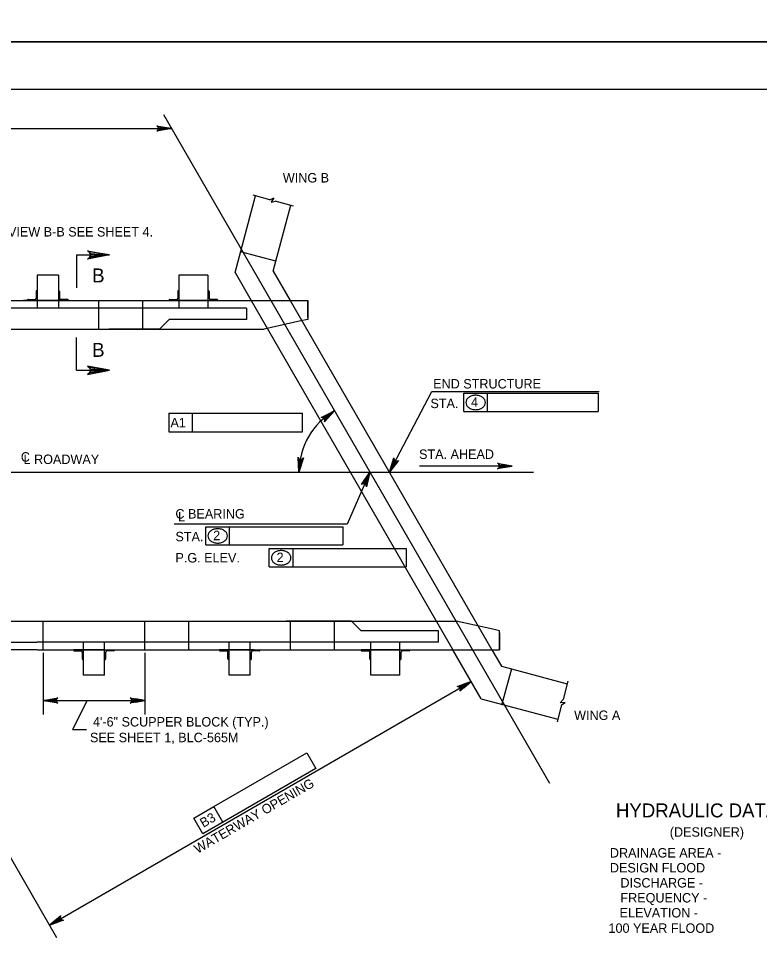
# Model space of a CAD drawing. Extents: x 638175 to 640495, y 294277 to 298435.
# Drawn here: x 638651.1 to 638887, y 296962.4 to 297255 of the extents above; entities that cross this region are included whole.
import ezdxf

# ---------------------------------------------------------------- set-up
doc = ezdxf.new("R2010")
doc.units = 0
for name, color, linetype in [('2', 7, 'Continuous'), ('3', 7, 'Continuous'), ('4', 7, 'Continuous'), ('PLT-BNDY', 7, 'Continuous')]:
    doc.layers.add(name, color=color, linetype=linetype)

msp = doc.modelspace()

# ---------------------------------------------------------------- linework, layer by layer
at = {"layer": '2'}
for p, q in [((638475.46, 297232.46), (639261.46, 297232.46)), ((638720.07, 297174.06), (638726.61, 297198.47)), ((638733.09, 297177.67), (638737.86, 297195.46)), ((638669.66, 297179.67), (638669.66, 297169.18)), ((638669.66, 297179.67), (638680.14, 297179.67)), ((638733.09, 297177.67), (638721.85, 297180.68)), ((638732.25, 297174.51), (638733.09, 297177.67)), ((638720.07, 297174.06), (638725.21, 297165.16)), ((638732.25, 297174.51), (638737.65, 297165.16)), ((638663.83, 297173.26), (638657.11, 297173.26)), ((638663.83, 297173.26), (638657.11, 297173.26)), ((638663.83, 297173.26), (638657.11, 297173.26)), ((638657.11, 297173.26), (638657.11, 297162.77)), ((638663.83, 297173.26), (638663.83, 297162.77)), ((638711.45, 297173.26), (638702.21, 297173.26)), ((638702.21, 297173.26), (638702.21, 297162.77)), ((638711.45, 297173.26), (638711.45, 297162.77)), ((638656.74, 297168.08), (638656.74, 297165.89)), ((638656.92, 297168.26), (638657.11, 297168.26)), ((638657.11, 297168.26), (638657.11, 297165.17)), ((638664.01, 297168.26), (638663.83, 297168.26)), ((638663.83, 297168.26), (638663.83, 297165.17)), ((638664.2, 297168.08), (638664.2, 297165.89)), ((638701.85, 297168.08), (638701.85, 297165.89)), ((638702.03, 297168.26), (638702.21, 297168.26)), ((638702.21, 297168.26), (638702.21, 297165.17)), ((638711.63, 297168.26), (638711.45, 297168.26)), ((638711.45, 297168.26), (638711.45, 297165.17)), ((638711.81, 297168.08), (638711.81, 297165.89)), ((638531.33, 297165.17), (638743.21, 297165.17)), ((638596.1, 297165.17), (638743.2, 297165.17)), ((638655.85, 297165.17), (638652.76, 297165.17)), ((638654.01, 297165.35), (638654.01, 297165.17)), ((638657.11, 297165.17), (638654.01, 297165.17)), ((638654.2, 297165.53), (638656.38, 297165.53)), ((638665.09, 297165.17), (638655.85, 297165.17)), ((638665.09, 297165.17), (638655.85, 297165.17)), ((638663.83, 297165.17), (638657.11, 297165.17)), ((638663.83, 297165.17), (638666.92, 297165.17)), ((638666.74, 297165.53), (638664.56, 297165.53)), ((638665.09, 297165.17), (638668.18, 297165.17)), ((638666.92, 297165.35), (638666.92, 297165.17)), ((638676.64, 297165.17), (638676.64, 297156.04)), ((638690.66, 297165.17), (638690.66, 297156.04)), ((638699.12, 297165.35), (638699.12, 297165.17)), ((638702.21, 297165.17), (638699.12, 297165.17)), ((638699.31, 297165.53), (638701.49, 297165.53)), ((638711.45, 297165.17), (638702.21, 297165.17)), ((638711.45, 297165.17), (638714.54, 297165.17)), ((638714.36, 297165.53), (638712.18, 297165.53)), ((638714.54, 297165.35), (638714.54, 297165.17)), ((638725.21, 297165.16), (638789.4, 297053.99)), ((638737.65, 297165.16), (638801.83, 297053.99)), ((638743.2, 297159.78), (638743.2, 297165.17)), ((638743.2, 297165.17), (638743.2, 297159.14)), ((638743.21, 297159.78), (638743.21, 297165.17)), ((638723.77, 297162.77), (638595.93, 297162.77)), ((638723.77, 297162.77), (638723.77, 297159.14)), ((638696.04, 297156.04), (638699.14, 297159.14)), ((638723.77, 297159.14), (638699.14, 297159.14)), ((638743.2, 297159.14), (638741.02, 297158.65)), ((638578.48, 297156.04), (638729.35, 297156.04)), ((638696.04, 297156.04), (638679.88, 297156.04)), ((638741.02, 297158.65), (638729.35, 297156.04)), ((638669.66, 297142.94), (638669.66, 297153.42)), ((638669.66, 297142.94), (638680.14, 297142.94)), ((638639.57, 297063.11), (638655.73, 297063.11)), ((638639.57, 297063.11), (638790.44, 297063.11)), ((638659.03, 297053.99), (638659.03, 297063.11)), ((638691.36, 297053.99), (638691.37, 297063.11)), ((638705.39, 297053.99), (638705.39, 297063.11)), ((638757.13, 297063.11), (638736.36, 297063.11)), ((638737.73, 297053.99), (638737.73, 297063.11)), ((638751.75, 297053.99), (638751.75, 297063.11)), ((638757.13, 297063.11), (638760.22, 297060.02)), ((638802.11, 297060.51), (638790.44, 297063.11)), ((638784.86, 297060.02), (638760.22, 297060.02)), ((638784.86, 297056.39), (638784.86, 297060.02)), ((638804.29, 297060.02), (638802.11, 297060.51)), ((638804.29, 297053.99), (638804.29, 297060.02)), ((638804.29, 297059.37), (638804.29, 297053.99)), ((638611.85, 297056.39), (638657.02, 297056.39)), ((638784.86, 297056.39), (638657.02, 297056.39)), ((638671.83, 297045.9), (638671.83, 297056.39)), ((638678.56, 297045.9), (638678.56, 297056.39)), ((638718.2, 297045.9), (638718.2, 297056.39)), ((638724.92, 297045.9), (638724.92, 297056.39)), ((638763.3, 297045.9), (638763.3, 297056.39)), ((638772.54, 297045.9), (638772.54, 297056.39)), ((638657.12, 297053.99), (638633.4, 297053.99)), ((638657.19, 297053.99), (638804.29, 297053.99)), ((638668.74, 297053.81), (638668.74, 297053.99)), ((638671.83, 297053.99), (638668.74, 297053.99)), ((638668.92, 297053.63), (638671.1, 297053.63)), ((638678.56, 297053.99), (638671.83, 297053.99)), ((638671.83, 297050.9), (638671.83, 297053.99)), ((638678.56, 297050.9), (638678.56, 297053.99)), ((638678.56, 297053.99), (638681.65, 297053.99)), ((638681.47, 297053.63), (638679.29, 297053.63)), ((638681.65, 297053.81), (638681.65, 297053.99)), ((638715.1, 297053.81), (638715.1, 297053.99)), ((638718.2, 297053.99), (638715.1, 297053.99)), ((638715.29, 297053.63), (638717.47, 297053.63)), ((638726.18, 297053.99), (638716.94, 297053.99)), ((638724.92, 297053.99), (638718.2, 297053.99)), ((638718.2, 297050.9), (638718.2, 297053.99)), ((638724.92, 297050.9), (638724.92, 297053.99)), ((638724.92, 297053.99), (638728.01, 297053.99)), ((638727.83, 297053.63), (638725.65, 297053.63)), ((638728.01, 297053.81), (638728.01, 297053.99)), ((638760.21, 297053.81), (638760.21, 297053.99)), ((638763.3, 297053.99), (638760.21, 297053.99)), ((638760.39, 297053.63), (638762.58, 297053.63)), ((638772.54, 297053.99), (638763.3, 297053.99)), ((638763.3, 297050.9), (638763.3, 297053.99)), ((638772.54, 297050.9), (638772.54, 297053.99)), ((638772.54, 297053.99), (638775.63, 297053.99)), ((638775.45, 297053.63), (638773.27, 297053.63)), ((638775.63, 297053.81), (638775.63, 297053.99)), ((638798.39, 297038.42), (638789.4, 297053.99)), ((638801.83, 297053.99), (638804.86, 297048.74)), ((638671.47, 297051.08), (638671.47, 297053.27)), ((638671.65, 297050.9), (638671.83, 297050.9)), ((638678.74, 297050.9), (638678.56, 297050.9)), ((638678.92, 297051.08), (638678.92, 297053.27)), ((638717.83, 297051.08), (638717.83, 297053.27)), ((638718.01, 297050.9), (638718.2, 297050.9)), ((638725.1, 297050.9), (638724.92, 297050.9)), ((638725.29, 297051.08), (638725.29, 297053.27)), ((638762.94, 297051.08), (638762.94, 297053.27)), ((638763.12, 297050.9), (638763.3, 297050.9)), ((638772.72, 297050.9), (638772.54, 297050.9)), ((638772.9, 297051.08), (638772.9, 297053.27)), ((638804.86, 297048.74), (638808.02, 297047.89)), ((638808.02, 297047.89), (638805, 297036.65)), ((638808.02, 297047.89), (638825.81, 297043.12)), ((638678.56, 297045.9), (638671.83, 297045.9)), ((638724.92, 297045.9), (638718.2, 297045.9)), ((638724.92, 297045.9), (638718.2, 297045.9)), ((638772.54, 297045.9), (638763.3, 297045.9)), ((638798.39, 297038.42), (638822.79, 297031.88))]:
    msp.add_line(p, q, dxfattribs=at)
for points in [[(638680.14, 297179.67), (638673.15, 297178.36), (638673.69, 297178.73), (638673.97, 297179.2), (638674.05, 297179.67), (638673.97, 297180.14), (638673.69, 297180.61), (638673.15, 297180.98), (638680.14, 297179.67), (638673.69, 297180.61), (638673.97, 297180.14), (638680.14, 297179.67), (638674.05, 297179.67), (638673.97, 297179.2), (638680.14, 297179.67), (638673.69, 297178.73)], [(638680.14, 297142.94), (638673.15, 297144.25), (638673.69, 297143.87), (638673.97, 297143.41), (638674.05, 297142.94), (638673.97, 297142.47), (638673.69, 297142), (638673.15, 297141.63), (638680.14, 297142.94), (638673.69, 297142), (638673.97, 297142.47), (638680.14, 297142.94), (638674.05, 297142.94), (638673.97, 297143.41), (638680.14, 297142.94), (638673.69, 297143.87)]]:
    msp.add_lwpolyline(points, dxfattribs=at)
for centre, radius, start, end in [((638656.92, 297168.08), 0.182, 90, 179.9984), ((638664.01, 297168.08), 0.182, 0.0016, 90), ((638702.03, 297168.08), 0.182, 90, 179.9984), ((638711.63, 297168.08), 0.182, 0.0016, 90), ((638654.2, 297165.35), 0.182, 90, 179.9984), ((638656.38, 297165.89), 0.364, 270, 359.9984), ((638664.56, 297165.89), 0.364, 180.0016, 270), ((638666.74, 297165.35), 0.182, 0.0016, 90), ((638699.31, 297165.35), 0.182, 90, 179.9984), ((638701.49, 297165.89), 0.364, 270, 359.9984), ((638712.18, 297165.89), 0.364, 180.0016, 270), ((638714.36, 297165.35), 0.182, 0.0016, 90), ((638668.92, 297053.81), 0.182, 180.0016, 270), ((638671.1, 297053.27), 0.364, 0.0016, 90), ((638679.29, 297053.27), 0.364, 90, 179.9984), ((638681.47, 297053.81), 0.182, 270, 359.9984), ((638715.29, 297053.81), 0.182, 180.0016, 270), ((638717.47, 297053.27), 0.364, 0.0016, 90), ((638725.65, 297053.27), 0.364, 90, 179.9984), ((638727.83, 297053.81), 0.182, 270, 359.9984), ((638760.39, 297053.81), 0.182, 180.0016, 270), ((638762.58, 297053.27), 0.364, 0.0016, 90), ((638773.27, 297053.27), 0.364, 90, 179.9984), ((638775.45, 297053.81), 0.182, 270, 359.9984), ((638671.65, 297051.08), 0.182, 180.0016, 270), ((638678.74, 297051.08), 0.182, 270, 359.9984), ((638718.01, 297051.08), 0.182, 180.0016, 270), ((638725.1, 297051.08), 0.182, 270, 359.9984), ((638763.12, 297051.08), 0.182, 180.0016, 270), ((638772.72, 297051.08), 0.182, 270, 359.9984)]:
    msp.add_arc(centre, radius, start, end, dxfattribs=at)
at = {"layer": '3'}
for p, q in [((638697.27, 297224.34), (638820.13, 297011.53)), ((638731.16, 297197.25), (638725.82, 297198.68)), ((638731.16, 297197.25), (638732.41, 297197.79)), ((638732.41, 297197.79), (638731.55, 297196.49)), ((638731.55, 297196.49), (638732.89, 297196.79)), ((638738.73, 297195.22), (638732.89, 297196.79)), ((638826.04, 297043.99), (638824.48, 297038.16)), ((638824.01, 297036.42), (638822.58, 297031.09)), ((638823.55, 297037.15), (638824.48, 297038.16)), ((638825.11, 297037.24), (638823.55, 297037.15)), ((638824.01, 297036.42), (638825.11, 297037.24))]:
    msp.add_line(p, q, dxfattribs=at)
at = {"layer": '4'}
for p, q in [((638508.41, 297219.92), (638699.81, 297219.92)), ((638769.19, 297110.53), (638782.76, 297136.25)), ((638782.76, 297136.25), (638835.95, 297136.25)), ((638792.86, 297135.63), (638800.44, 297135.63)), ((638792.86, 297129.87), (638792.86, 297135.63)), ((638800.44, 297129.87), (638800.44, 297135.63)), ((638800.44, 297135.63), (638835.62, 297135.63)), ((638835.62, 297135.63), (638835.62, 297129.87)), ((638792.86, 297129.87), (638835.62, 297129.87)), ((638699, 297129.26), (638698.99, 297123.36)), ((638699, 297129.26), (638706.56, 297129.26)), ((638706.56, 297123.36), (638706.56, 297129.26)), ((638706.56, 297129.26), (638741.52, 297129.26)), ((638741.51, 297123.36), (638741.52, 297129.26)), ((638698.99, 297123.36), (638741.51, 297123.36)), ((638805.42, 297112.46), (638778.78, 297112.46)), ((638530.06, 297110.53), (638815.07, 297110.53)), ((638762.97, 297110.53), (638755.79, 297093.93)), ((638755.79, 297093.93), (638700.72, 297093.93)), ((638710.77, 297093.17), (638718.35, 297093.17)), ((638710.77, 297087.4), (638710.77, 297093.17)), ((638718.35, 297087.4), (638718.35, 297093.17)), ((638718.35, 297093.17), (638754.35, 297093.17)), ((638754.35, 297093.17), (638754.35, 297087.4)), ((638710.77, 297087.4), (638754.35, 297087.4)), ((638730.96, 297080.43), (638730.96, 297086.2)), ((638730.96, 297086.2), (638738.54, 297086.2)), ((638738.54, 297080.43), (638738.54, 297086.2)), ((638738.54, 297086.2), (638774.54, 297086.2)), ((638774.54, 297086.2), (638774.54, 297080.43)), ((638730.96, 297080.43), (638774.54, 297080.43)), ((638659.03, 297053.06), (638659.03, 297033.43)), ((638691.36, 297053.06), (638691.36, 297033.43)), ((638616.34, 297043.74), (638663.26, 296962.47)), ((638661.02, 296966.36), (638795.25, 297043.86)), ((638659.03, 297037.86), (638691.36, 297037.86)), ((638672.98, 297037.86), (638668.39, 297028.63)), ((638668.39, 297028.63), (638672.82, 297028.63)), ((638713.34, 297004.12), (638742.92, 297021.16)), ((638742.92, 297021.16), (638745.8, 297016.16)), ((638745.8, 297016.16), (638709.82, 296995.43)), ((638706.94, 297000.43), (638713.34, 297004.12)), ((638716.22, 296999.12), (638713.34, 297004.12)), ((638709.82, 296995.43), (638706.94, 297000.43))]:
    msp.add_line(p, q, dxfattribs=at)
for points in [[(638699.81, 297219.92), (638695.15, 297219.05), (638695.51, 297219.3), (638695.7, 297219.61), (638695.75, 297219.92), (638695.7, 297220.24), (638695.51, 297220.55), (638695.15, 297220.8), (638699.81, 297219.92), (638695.51, 297220.55), (638695.7, 297220.24), (638699.81, 297219.92), (638695.75, 297219.92), (638695.7, 297219.61), (638699.81, 297219.92), (638695.51, 297219.3)], [(638751.7, 297130.05), (638748.53, 297126.53), (638748.66, 297126.94), (638748.62, 297127.3), (638748.47, 297127.58), (638748.24, 297127.8), (638747.91, 297127.93), (638747.47, 297127.91), (638751.7, 297130.05), (638747.91, 297127.93), (638748.24, 297127.8), (638751.7, 297130.05), (638748.47, 297127.58), (638748.62, 297127.3), (638751.7, 297130.05), (638748.66, 297126.94)], [(638740.43, 297110.52), (638740.14, 297115.25), (638740.34, 297114.86), (638740.63, 297114.64), (638740.93, 297114.55), (638741.25, 297114.57), (638741.58, 297114.71), (638741.87, 297115.04), (638740.43, 297110.52), (638741.58, 297114.71), (638741.25, 297114.57), (638740.43, 297110.52), (638740.93, 297114.55), (638740.63, 297114.64), (638740.43, 297110.52), (638740.34, 297114.86)], [(638769.19, 297110.53), (638770.59, 297115.06), (638770.64, 297114.63), (638770.83, 297114.32), (638771.08, 297114.12), (638771.38, 297114.03), (638771.75, 297114.05), (638772.13, 297114.25), (638769.19, 297110.53), (638771.75, 297114.05), (638771.38, 297114.03), (638769.19, 297110.53), (638771.08, 297114.12), (638770.83, 297114.32), (638769.19, 297110.53), (638770.64, 297114.63)], [(638808.31, 297112.46), (638803.65, 297111.59), (638804, 297111.84), (638804.19, 297112.15), (638804.24, 297112.46), (638804.19, 297112.78), (638804, 297113.09), (638803.65, 297113.34), (638808.31, 297112.46), (638804, 297113.09), (638804.19, 297112.78), (638808.31, 297112.46), (638804.24, 297112.46), (638804.19, 297112.15), (638808.31, 297112.46), (638804, 297111.84)], [(638762.97, 297110.53), (638761.92, 297105.91), (638761.84, 297106.34), (638761.62, 297106.63), (638761.36, 297106.8), (638761.05, 297106.88), (638760.69, 297106.83), (638760.32, 297106.6), (638762.97, 297110.53), (638760.69, 297106.83), (638761.05, 297106.88), (638762.97, 297110.53), (638761.36, 297106.8), (638761.62, 297106.63), (638762.97, 297110.53), (638761.84, 297106.34)], [(638795.25, 297043.86), (638791.65, 297040.77), (638791.84, 297041.17), (638791.84, 297041.53), (638791.73, 297041.83), (638791.53, 297042.07), (638791.21, 297042.25), (638790.77, 297042.29), (638795.25, 297043.86), (638791.21, 297042.25), (638791.53, 297042.07), (638795.25, 297043.86), (638791.73, 297041.83), (638791.84, 297041.53), (638795.25, 297043.86), (638791.84, 297041.17)], [(638659.03, 297037.86), (638663.69, 297038.73), (638663.33, 297038.48), (638663.14, 297038.17), (638663.09, 297037.86), (638663.14, 297037.54), (638663.33, 297037.23), (638663.69, 297036.98), (638659.03, 297037.86), (638663.33, 297037.23), (638663.14, 297037.54), (638659.03, 297037.86), (638663.09, 297037.86), (638663.14, 297038.17), (638659.03, 297037.86), (638663.33, 297038.48)], [(638691.36, 297037.86), (638686.7, 297036.98), (638687.06, 297037.23), (638687.25, 297037.54), (638687.3, 297037.86), (638687.25, 297038.17), (638687.06, 297038.48), (638686.7, 297038.73), (638691.36, 297037.86), (638687.06, 297038.48), (638687.25, 297038.17), (638691.36, 297037.86), (638687.3, 297037.86), (638687.25, 297037.54), (638691.36, 297037.86), (638687.06, 297037.23)], [(638661.02, 296966.36), (638664.62, 296969.45), (638664.43, 296969.05), (638664.42, 296968.69), (638664.53, 296968.39), (638664.74, 296968.15), (638665.05, 296967.97), (638665.49, 296967.93), (638661.02, 296966.36), (638665.05, 296967.97), (638664.74, 296968.15), (638661.02, 296966.36), (638664.53, 296968.39), (638664.42, 296968.69), (638661.02, 296966.36), (638664.43, 296969.05)]]:
    msp.add_lwpolyline(points, dxfattribs=at)
for points in [[(638805.42, 297112.95), (638805.42, 297111.98), (638808.31, 297112.46)], [(638762.25, 297107.63), (638761.35, 297108.02), (638762.97, 297110.53)], [(638792.4, 297042.8), (638792.9, 297041.93), (638795.25, 297043.86)], [(638661.98, 297038.35), (638661.98, 297037.36), (638659.03, 297037.86)], [(638688.41, 297038.35), (638688.41, 297037.36), (638691.36, 297037.86)], [(638663.36, 296968.29), (638663.86, 296967.43), (638661.01, 296966.36)], [(638663.86, 296967.43), (638663.36, 296968.29), (638661.02, 296966.36)]]:
    msp.add_lwpolyline(points, close=True, dxfattribs=at)
for centre, radius, start, end in [((638795.24, 297132.7), 1.71, 150.6308, 180), ((638795.24, 297132.7), 1.71, 180, 209.3692), ((638795.92, 297132.32), 2.49, 126.3544, 150.6308), ((638796.36, 297131.72), 3.23, 106.9552, 126.3544), ((638796.65, 297130.78), 4.22, 90, 106.9552), ((638796.65, 297130.78), 4.22, 73.0448, 90), ((638796.94, 297131.72), 3.23, 53.6456, 73.0448), ((638797.38, 297132.32), 2.49, 29.3692, 53.6456), ((638798.05, 297132.7), 1.71, 0, 29.3692), ((638798.05, 297132.7), 1.71, 330.6308, 0), ((638762.97, 297110.53), 22.54, 119.9992, 179.9979), ((638795.92, 297133.08), 2.49, 209.3692, 233.6456), ((638796.36, 297133.68), 3.23, 233.6456, 253.0448), ((638796.65, 297134.63), 4.22, 253.0448, 270), ((638796.65, 297134.63), 4.22, 270, 286.9552), ((638796.94, 297133.68), 3.23, 286.9552, 306.3544), ((638797.38, 297133.08), 2.49, 306.3544, 330.6308), ((638713.82, 297089.85), 2.49, 126.3544, 150.6308), ((638714.27, 297089.25), 3.23, 106.9552, 126.3544), ((638714.55, 297088.31), 4.22, 90, 106.9552), ((638714.55, 297088.31), 4.22, 73.0448, 90), ((638714.84, 297089.25), 3.23, 53.6456, 73.0448), ((638715.28, 297089.85), 2.49, 29.3692, 53.6456), ((638713.15, 297090.24), 1.71, 150.6308, 180), ((638713.15, 297090.24), 1.71, 180, 209.3692), ((638713.82, 297090.62), 2.49, 209.3692, 233.6456), ((638714.27, 297091.22), 3.23, 233.6456, 253.0448), ((638714.84, 297091.22), 3.23, 286.9552, 306.3544), ((638715.28, 297090.62), 2.49, 306.3544, 330.6308), ((638715.96, 297090.24), 1.71, 0, 29.3692), ((638715.96, 297090.24), 1.71, 330.6308, 0), ((638714.55, 297092.16), 4.22, 253.0448, 270), ((638714.55, 297092.16), 4.22, 270, 286.9552), ((638733.34, 297083.27), 1.71, 150.6308, 180), ((638733.34, 297083.27), 1.71, 180, 209.3692), ((638734.01, 297082.89), 2.49, 126.3544, 150.6308), ((638734.45, 297082.29), 3.23, 106.9552, 126.3544), ((638734.74, 297081.34), 4.22, 90, 106.9552), ((638734.74, 297081.34), 4.22, 73.0448, 90), ((638735.03, 297082.29), 3.23, 53.6456, 73.0448), ((638735.47, 297082.89), 2.49, 29.3692, 53.6456), ((638736.15, 297083.27), 1.71, 0, 29.3692), ((638736.15, 297083.27), 1.71, 330.6308, 0), ((638734.01, 297083.65), 2.49, 209.3692, 233.6456), ((638734.45, 297084.25), 3.23, 233.6456, 253.0448), ((638734.74, 297085.19), 4.22, 253.0448, 270), ((638734.74, 297085.19), 4.22, 270, 286.9552), ((638735.03, 297084.25), 3.23, 286.9552, 306.3544), ((638735.47, 297083.65), 2.49, 306.3544, 330.6308)]:
    msp.add_arc(centre, radius, start, end, dxfattribs=at)
at = {"layer": 'PLT-BNDY'}
for points in [[(638435.46, 297841.46), (639276.46, 297841.46), (639276.46, 297247.46), (638435.46, 297247.46)], [(638435.46, 297247.46), (639276.46, 297247.46), (639276.46, 296653.46), (638435.46, 296653.46)]]:
    msp.add_lwpolyline(points, close=True, dxfattribs=at)

# ---------------------------------------------------------------- texts
at = {"layer": '4'}
for s, height, p in [('WING B', 3, (638735.29, 297202.72)), ('FOR VIEW B-B SEE SHEET 4.', 3, (638638.23, 297185.53)), ('B', 4.43, (638674.6, 297147.23)), ('END STRUCTURE', 3, (638783.14, 297137.16)), ('STA.', 3, (638782.27, 297130.92)), ('4', 3, (638795.2, 297131.35)), ('STA. AHEAD', 3, (638778.64, 297114.75)), ('C', 3, (638651.9, 297113.88)), ('L ROADWAY', 3, (638652.76, 297113.13)), ('C BEARING', 3, (638701.1, 297095.77)), ('L', 3, (638701.92, 297094.86)), ('STA.', 3, (638701.1, 297088.53)), ('2', 3, (638713.1, 297088.88)), ('P.G. ELEV.', 3, (638701.1, 297081.78)), ('2', 3, (638733.29, 297081.92)), ('WING A', 3, (638828, 297031.66)), ('4\'-6" SCUPPER BLOCK (TYP.)', 3, (638674.85, 297029.57)), ('SEE SHEET 1, BLC-565M', 3, (638673.9, 297024.58)), ('HYDRAULIC DATA', 4.4292, (638841.31, 297000.66)), ('(DESIGNER)', 3, (638858.45, 296994.5)), ('DRAINAGE AREA - ', 3, (638839.39, 296987.87)), ('DESIGN FLOOD  ', 3, (638839.39, 296983.12)), ('   DISCHARGE - ', 3, (638839.39, 296978.33)), ('   FREQUENCY - ', 3, (638839.39, 296973.56)), ('   ELEVATION - ', 3, (638839.12, 296968.79)), ('100 YEAR FLOOD', 3, (638838.94, 296963.9))]:
    msp.add_text(s, height=height, dxfattribs=at).set_placement(p)
for s, height, rotation, p in [('B', 4.43, 360, (638674.6, 297170.94)), ('A1', 3, 359.9382, (638699.51, 297124.81)), ('WATERWAY OPENING', 3, 30, (638708.15, 296989.03)), ('B3', 3, 29.9438, (638709.98, 296997.29))]:
    msp.add_text(s, height=height, rotation=rotation, dxfattribs=at).set_placement(p)

doc.saveas('drawing.dxf')
